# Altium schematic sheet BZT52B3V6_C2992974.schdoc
size 127 x 101 mm
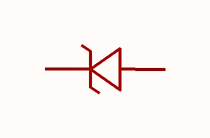
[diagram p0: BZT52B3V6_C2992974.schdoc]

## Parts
D?  bzt52b3v6_c2992974  [SOD-123F_L2.7-W1.7-LS3.7-RD-2]  (value not drawn)

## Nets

Not connected (* = marked no-connect by the designer): D? 1(K) 2(A)

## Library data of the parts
D? = bzt52b3v6_c2992974: 二极管配置:1个独立式;稳压值(标称值):3.6V;稳压值(范围):3.53V~3.67V;耗散功率(Pd):500mW;; Manufacturer: MDD(辰达半导体); AddInBom: yes; ModelId: 745faf9ecaa14675bdb7e3f6c3f6310a; ModelTransform: 145.669,66.929,0,0,0,0,0,0,0; Diode Configuration: 1个独立式; Zener Voltage(Nom): 3.6V; Reverse Leakage Current (Ir): 10uA@1V; Pd - Power Dissipation: 500mW; Impedance(Zzt): 130Ω; Tolerance: ±2%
